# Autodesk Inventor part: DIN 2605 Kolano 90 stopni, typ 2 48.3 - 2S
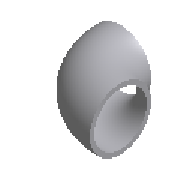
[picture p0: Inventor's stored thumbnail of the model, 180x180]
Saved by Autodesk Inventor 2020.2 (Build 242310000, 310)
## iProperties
Manager: www.cadconsulting.pl
Company: Fabian Stasiak CAD Consulting
NAME: PIPING: DIN 2605 90 Deg Elbow Type 2
DATA: <meta><inlinegroups number="0" deflen="0"></inlinegroups><connections number="2"></connections><angles><a>1.57079632679489</a></angles></meta>
IsCustomPart: 0
Created: 2014-02
Part Number: DIN 2605 Kolano 90 stopni, typ 2 48.3 - 2S
Material: Stal
Description: Kolano
Document SubType Name: Modeling
Standard: DIN 2605
Designer: F.Stasiak
Standards Organization: DIN
Language: pl-PL
Size Designation: 48.3 - 2S
Categories: <MemberInstance><Categories><Category DisplayName="Rury cienko- i grubościenne" InternalName="4347fa0f-2144-441d-94cd-e3e15c92b736" Mnemonic="TUBEANDPIPE"><Cate
Density: 1 g/cm^3
Appearance: Płyta
Catalog Web Link: www.expertbooks.pl
Author: F.Stasiak
Subject: Zbiór ćwiczeń. Autodesk Inventor 2020. Kurs Professional
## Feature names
1. Sweep1
## Parameters: d0 = 44.3 mm, d1 = 48.3 mm, da = 48.3 mm, r = 38 mm, d2 = 38 mm, d3 = 38 mm, d4 = 0, s1 = 2 mm, d5 = 0, Size_Designation = 12.345 mm
